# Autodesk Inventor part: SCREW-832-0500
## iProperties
Created: 2007-08
Part Number: SCREW-832-0500
Material: Stainless Steel
Document SubType Name: Modeling
Density: 8.08 g/cm^3
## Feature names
1. Base1
